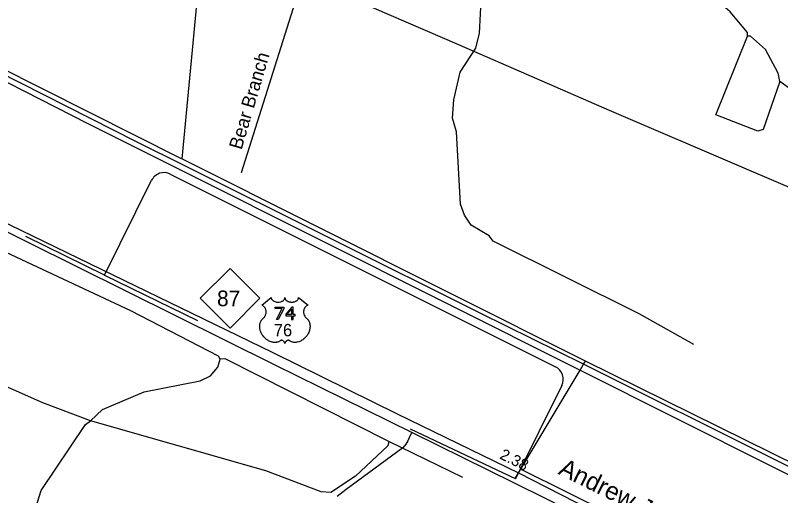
# Model space of a CAD drawing. Extents: x 2225501 to 2309677, y 165449 to 227696.
# Drawn here: x 2244504 to 2253045, y 199877 to 205240 of the extents above; entities that cross this region are included whole.
import ezdxf

# ---------------------------------------------------------------- set-up
doc = ezdxf.new("R2010")
doc.units = 0
for name, color, linetype in [('Black Area Fill Shapes', 7, 'Continuous'), ('Collision Diagram Indicator Injury CELL', 7, 'Continuous'), ('Old_Level_3', 7, 'Continuous'), ('Old_Level_46', 7, 'Continuous'), ('P_HYD_Ditch_Flow_Line', 7, 'Continuous'), ('P_HYD_Junction_Box_with_Slab_Lid_840_31_15_Dia-Top_CELL', 7, 'Continuous'), ('P_HYD_RipRap_Pad_876_02_18in_Outlet_With_Ditch-Top_CELL', 7, 'Continuous'), ('P_HYD_RipRap_Pad_876_02_18in_Outlet_With_Ditch_CELL', 7, 'Continuous'), ('Prop Support', 7, 'Continuous'), ('Raster_Level_0', 7, 'Continuous'), ('Scratch_Level_1', 7, 'Continuous'), ('Scratch_Level_2', 7, 'Continuous'), ('Typical Terminator CELL', 7, 'Continuous')]:
    doc.layers.add(name, color=color, linetype=linetype)

msp = doc.modelspace()

# ---------------------------------------------------------------- linework, layer by layer
at = {"layer": 'Black Area Fill Shapes'}
for points in [[(2244873.1, 206903.9), (2245139.4, 206787.1), (2246595.9, 206147.3), (2247912.2, 205580.4), (2249458.9, 204911.2), (2251132.3, 204181.1), (2252660.9, 203525.9), (2253800.5, 203037.4), (2255064.4, 202491.9), (2255394, 202351.2)], [(2246387.7, 203561.8), (2245857.2, 203826.2), (2244048.6, 204743.1), (2243731.3, 204902.7)], [(2243706.2, 204852.1), (2245311.8, 204031.6), (2246428.1, 203472.8)], [(2250845.6, 201345.2), (2249697.4, 201912.2), (2246387.7, 203561.8)], [(2246428.1, 203472.8), (2249284.4, 202042.9), (2250805.9, 201279)], [(2254290.5, 199620.9), (2252914.9, 200311.1), (2250919.7, 201308.6), (2250845.6, 201345.2)], [(2250805.9, 201279), (2252943.9, 200205.6), (2254260.8, 199546.4)]]:
    msp.add_lwpolyline(points, dxfattribs=at)
at = {"layer": 'Collision Diagram Indicator Injury CELL'}
for p, q in [((2246233.2, 203467.5), (2250532.4, 201316)), ((2245499.3, 202339.4), (2246025, 203397.8)), ((2245499.3, 202339.4), (2244623.1, 202770.9)), ((2245499.3, 202339.4), (2246537.6, 201834.2)), ((2250601.9, 201108.4), (2250084.5, 200066.8)), ((2250084.5, 200066.8), (2248914.6, 200621)), ((2250152, 200168.1), (2251904.7, 199305.8))]:
    msp.add_line(p, q, dxfattribs=at)
for centre, start, end in [((2246163.9, 203328.8), 63.41515, 153.58531), ((2250463.1, 201177.4), 333.58531, 63.41515)]:
    msp.add_arc(centre, 155, start, end, dxfattribs=at)
at = {"layer": 'Old_Level_3'}
for p, q in [((2246537.5, 205467.2), (2246362.6, 203636.4)), ((2246351.4, 203642.1), (2243753, 204946.6)), ((2246362.6, 203636.4), (2246351.4, 203642.1)), ((2250865.3, 201378), (2246362.6, 203636.4)), ((2250805.9, 201279), (2250845.6, 201345.2)), ((2250845.6, 201345.2), (2250865.3, 201378)), ((2253336.1, 200158.7), (2250865.3, 201378)), ((2250114.3, 200125.3), (2250805.9, 201279)), ((2248900.8, 200521.7), (2248883.2, 200488.2))]:
    msp.add_line(p, q, dxfattribs=at)
for points in [[(2248900.8, 200521.7), (2248926.6, 200570.6), (2248933.2, 200581.2)], [(2248883.2, 200488.2), (2248861.5, 200452.1), (2248829.9, 200411.9), (2248197.8, 199946.9), (2248095.2, 199869.5)], [(2250080.7, 200066.4), (2250086.1, 200078.3), (2250114.3, 200125.3)]]:
    msp.add_lwpolyline(points, dxfattribs=at)
at = {"layer": 'Old_Level_46'}
for points in [[(2256956.7, 196790), (2256924.7, 196796.5), (2256832.3, 196817.3), (2256652.3, 196875.8), (2256591.1, 196902.4), (2256480.1, 196951.1), (2256338.5, 197006.2), (2256282.6, 197031), (2254541.8, 197924.5), (2254210.5, 198073.2), (2253786.6, 198278.1), (2252185.6, 199073.8), (2250121.7, 200127.7), (2248768.8, 200789.1), (2247375.2, 201475.6), (2243675.2, 203270.8), (2243284.4, 203458.4), (2243017.1, 203588.4)], [(2242986.4, 203530.7), (2247394.3, 201340.7), (2248933.2, 200581.2), (2250061.9, 200025.4), (2252258.3, 198936.4), (2253668.1, 198237.8), (2254159.3, 197994.4), (2254220.9, 197964), (2255278.5, 197442.7), (2256250.7, 196963.5), (2256279.6, 196949.9), (2256416.4, 196885.1), (2256553.4, 196820.3), (2256635.4, 196787.9), (2256780.8, 196739.2), (2256905.8, 196709.8), (2256941.4, 196700.5), (2256960.1, 196697.4)]]:
    msp.add_lwpolyline(points, dxfattribs=at)
at = {"layer": 'P_HYD_Ditch_Flow_Line'}
for points in [[(2247499.4, 201961.7), (2247437.2, 201844.7), (2247417.4, 201844.7), (2247483.4, 201966), (2247405.3, 201966), (2247405.3, 201982.2), (2247499.4, 201982.2)], [(2247625.4, 201883.4), (2247625.4, 201898.2), (2247605, 201898.2), (2247605, 201982.2), (2247588, 201982.2), (2247521.4, 201904.7), (2247521.4, 201883.4), (2247587.2, 201883.4), (2247587.2, 201844.7), (2247605, 201844.7), (2247605, 201883.4)], [(2247587.2, 201898.2), (2247533.9, 201898.2), (2247587.2, 201960.3)]]:
    msp.add_lwpolyline(points, close=True, dxfattribs=at)
at = {"layer": 'P_HYD_Junction_Box_with_Slab_Lid_840_31_15_Dia-Top_CELL'}
for p, q in [((2246567.8, 202082.2), (2246900.8, 202415.2)), ((2246900.8, 202415.2), (2247233.8, 202082.2)), ((2246900.8, 201749.2), (2246567.8, 202082.2)), ((2247233.8, 202082.2), (2246900.8, 201749.2))]:
    msp.add_line(p, q, dxfattribs=at)
at = {"layer": 'P_HYD_RipRap_Pad_876_02_18in_Outlet_With_Ditch-Top_CELL'}
for p, q in [((2247253.8, 202004.1), (2247360.1, 202088.8)), ((2247360.1, 202088.8), (2247360.4, 202084.4)), ((2247360.4, 202084.4), (2247361.4, 202079.2)), ((2247511.1, 202080.3), (2247511.7, 202083.1)), ((2247511.7, 202083.1), (2247512.2, 202089)), ((2247512.2, 202089), (2247512.6, 202084.1)), ((2247512.6, 202084.1), (2247513.1, 202081)), ((2247662.6, 202078), (2247663.7, 202082.2)), ((2247663.7, 202082.2), (2247664.2, 202085.9)), ((2247664.2, 202085.9), (2247664.3, 202089.1)), ((2247664.3, 202089.1), (2247770.5, 202004.4)), ((2247257.1, 202002.8), (2247253.8, 202004.1)), ((2247262.3, 202000.2), (2247257.1, 202002.8)), ((2247267.7, 201996.9), (2247262.3, 202000.2)), ((2247272, 201993.9), (2247267.7, 201996.9)), ((2247361.4, 202079.2), (2247362.3, 202076.5)), ((2247362.3, 202076.5), (2247364.7, 202071.3)), ((2247364.7, 202071.3), (2247368.7, 202065.2)), ((2247368.7, 202065.2), (2247374.3, 202059.2)), ((2247374.3, 202059.2), (2247380.7, 202054)), ((2247380.7, 202054), (2247384.9, 202051.3)), ((2247384.9, 202051.3), (2247392.2, 202047.4)), ((2247392.2, 202047.4), (2247400.4, 202043.9)), ((2247400.4, 202043.9), (2247409.6, 202041.3)), ((2247409.6, 202041.3), (2247418.9, 202039.4)), ((2247418.9, 202039.4), (2247429.2, 202038.3)), ((2247429.2, 202038.3), (2247439.3, 202038.1)), ((2247439.3, 202038.1), (2247450.2, 202038.9)), ((2247450.2, 202038.9), (2247462.2, 202041.2)), ((2247462.2, 202041.2), (2247467.8, 202042.7)), ((2247467.8, 202042.7), (2247474, 202044.8)), ((2247474, 202044.8), (2247479.8, 202047.2)), ((2247479.8, 202047.2), (2247486.2, 202050.6)), ((2247486.2, 202050.6), (2247491.2, 202053.8)), ((2247491.2, 202053.8), (2247495.2, 202056.7)), ((2247495.2, 202056.7), (2247500.9, 202062.1)), ((2247500.9, 202062.1), (2247505.4, 202067.7)), ((2247505.4, 202067.7), (2247507.3, 202070.9)), ((2247507.3, 202070.9), (2247508.9, 202073.9)), ((2247508.9, 202073.9), (2247511.1, 202080.3)), ((2247513.1, 202081), (2247513.9, 202078)), ((2247513.9, 202078), (2247515.1, 202074.8)), ((2247515.1, 202074.8), (2247517.4, 202070.2)), ((2247517.4, 202070.2), (2247519.9, 202066.5)), ((2247519.9, 202066.5), (2247524.6, 202060.9)), ((2247524.6, 202060.9), (2247527.6, 202058.1)), ((2247527.6, 202058.1), (2247530.3, 202055.9)), ((2247530.3, 202055.9), (2247537.5, 202051)), ((2247537.5, 202051), (2247545.9, 202046.7)), ((2247545.9, 202046.7), (2247550.1, 202044.9)), ((2247550.1, 202044.9), (2247554.4, 202043.4)), ((2247554.4, 202043.4), (2247559.8, 202041.7)), ((2247559.8, 202041.7), (2247565.3, 202040.4)), ((2247565.3, 202040.4), (2247570.9, 202039.5)), ((2247570.9, 202039.5), (2247576.5, 202038.6)), ((2247576.5, 202038.6), (2247582.3, 202038.2)), ((2247582.3, 202038.2), (2247587, 202038.1)), ((2247587, 202038.1), (2247592.8, 202038.1)), ((2247592.8, 202038.1), (2247598.1, 202038.5)), ((2247598.1, 202038.5), (2247603.6, 202039.1)), ((2247603.6, 202039.1), (2247609.6, 202040.1)), ((2247609.6, 202040.1), (2247614.4, 202041.2)), ((2247614.4, 202041.2), (2247620.8, 202042.9)), ((2247620.8, 202042.9), (2247626.6, 202044.9)), ((2247626.6, 202044.9), (2247631.7, 202047.1)), ((2247631.7, 202047.1), (2247638.3, 202050.6)), ((2247638.3, 202050.6), (2247643.6, 202053.9)), ((2247643.6, 202053.9), (2247647.5, 202057.1)), ((2247647.5, 202057.1), (2247652.2, 202061.3)), ((2247652.2, 202061.3), (2247656.5, 202066.4)), ((2247656.5, 202066.4), (2247659.1, 202070.1)), ((2247659.1, 202070.1), (2247660.9, 202073.9)), ((2247660.9, 202073.9), (2247662.6, 202078)), ((2247757.7, 201998), (2247750.4, 201992.8)), ((2247762.3, 202000.7), (2247757.7, 201998)), ((2247768, 202003.5), (2247762.3, 202000.7)), ((2247770.5, 202004.4), (2247768, 202003.5)), ((2247276.5, 201990.4), (2247272, 201993.9)), ((2247281.2, 201985.6), (2247276.5, 201990.4)), ((2247285.9, 201980.4), (2247281.2, 201985.6)), ((2247290.4, 201973.9), (2247285.9, 201980.4)), ((2247294.5, 201966.9), (2247290.4, 201973.9)), ((2247296.9, 201961.8), (2247294.5, 201966.9)), ((2247299.6, 201954.7), (2247296.9, 201961.8)), ((2247301.2, 201948.6), (2247299.6, 201954.7)), ((2247302.6, 201941.6), (2247301.2, 201948.6)), ((2247301.2, 201907.8), (2247302.5, 201914.2)), ((2247302.5, 201914.2), (2247303.3, 201920.3)), ((2247303.4, 201934.2), (2247302.6, 201941.6)), ((2247303.3, 201920.3), (2247303.6, 201927.9)), ((2247303.6, 201927.9), (2247303.4, 201934.2)), ((2247721.1, 201935.6), (2247720.8, 201931.1)), ((2247720.8, 201931.1), (2247720.8, 201926.6)), ((2247720.8, 201926.6), (2247721, 201921.9)), ((2247721, 201921.9), (2247721.4, 201917.4)), ((2247722.3, 201945.1), (2247721.1, 201935.6)), ((2247721.4, 201917.4), (2247722.3, 201912.7)), ((2247723.3, 201949.7), (2247722.3, 201945.1)), ((2247722.3, 201912.7), (2247723, 201908.5)), ((2247724.9, 201955.1), (2247723.3, 201949.7)), ((2247728.2, 201963.6), (2247724.9, 201955.1)), ((2247730.1, 201967.7), (2247728.2, 201963.6)), ((2247732.8, 201972.4), (2247730.1, 201967.7)), ((2247735.6, 201976.7), (2247732.8, 201972.4)), ((2247738.7, 201980.9), (2247735.6, 201976.7)), ((2247741.2, 201983.9), (2247738.7, 201980.9)), ((2247744.1, 201987), (2247741.2, 201983.9)), ((2247747.2, 201990), (2247744.1, 201987)), ((2247750.4, 201992.8), (2247747.2, 201990)), ((2247242.2, 201821), (2247245.7, 201828.1)), ((2247245.7, 201828.1), (2247249, 201833.9)), ((2247249, 201833.9), (2247253.2, 201840.2)), ((2247253.2, 201840.2), (2247257.4, 201845.5)), ((2247257.4, 201845.5), (2247262.8, 201851.4)), ((2247262.8, 201851.4), (2247268.5, 201856.8)), ((2247268.5, 201856.8), (2247273.6, 201861.1)), ((2247273.6, 201861.1), (2247279.8, 201867.1)), ((2247279.8, 201867.1), (2247283, 201870.7)), ((2247283, 201870.7), (2247286.9, 201875.8)), ((2247286.9, 201875.8), (2247289.9, 201880.5)), ((2247289.9, 201880.5), (2247292.4, 201884.7)), ((2247292.4, 201884.7), (2247295.6, 201890.9)), ((2247295.6, 201890.9), (2247297.6, 201895.6)), ((2247297.6, 201895.6), (2247300, 201902.7)), ((2247300, 201902.7), (2247301.2, 201907.8)), ((2247723, 201908.5), (2247724.3, 201903.4)), ((2247724.3, 201903.4), (2247726.2, 201897.5)), ((2247726.2, 201897.5), (2247728.5, 201891.8)), ((2247728.5, 201891.8), (2247733.4, 201882.6)), ((2247733.4, 201882.6), (2247739.6, 201873.2)), ((2247739.6, 201873.2), (2247744.1, 201867.9)), ((2247744.1, 201867.9), (2247748.5, 201863.4)), ((2247748.5, 201863.4), (2247755.1, 201857.9)), ((2247755.1, 201857.9), (2247758.6, 201854.7)), ((2247758.6, 201854.7), (2247762.7, 201850.6)), ((2247762.7, 201850.6), (2247769.3, 201842.9)), ((2247769.3, 201842.9), (2247772, 201839.3)), ((2247772, 201839.3), (2247774.8, 201835.2)), ((2247774.8, 201835.2), (2247777.3, 201831)), ((2247777.3, 201831), (2247779.8, 201826.5)), ((2247779.8, 201826.5), (2247781.8, 201822.5)), ((2247231.2, 201769.6), (2247231.5, 201776.8)), ((2247231.4, 201761), (2247231.2, 201769.6)), ((2247232, 201751.7), (2247231.4, 201761)), ((2247231.5, 201776.8), (2247232.3, 201785.1)), ((2247233.2, 201742.8), (2247232, 201751.7)), ((2247232.3, 201785.1), (2247233.7, 201794)), ((2247234.4, 201736.3), (2247233.2, 201742.8)), ((2247233.7, 201794), (2247235.4, 201801.6)), ((2247235.4, 201801.6), (2247236.9, 201807)), ((2247236.9, 201807), (2247239.2, 201813.7)), ((2247239.2, 201813.7), (2247242.2, 201821)), ((2247781.8, 201822.5), (2247785.5, 201813.4)), ((2247785.5, 201813.4), (2247788.3, 201804.5)), ((2247788.3, 201804.5), (2247789.5, 201799.9)), ((2247789.5, 201799.9), (2247791.5, 201789.5)), ((2247792.1, 201750.1), (2247789.9, 201736.5)), ((2247791.5, 201789.5), (2247792.2, 201784.3)), ((2247793.1, 201761.8), (2247792.1, 201750.1)), ((2247792.2, 201784.3), (2247793.1, 201774.1)), ((2247793.1, 201774.1), (2247793.1, 201761.8)), ((2247236.4, 201727.2), (2247234.4, 201736.3)), ((2247237.9, 201722), (2247236.4, 201727.2)), ((2247240.5, 201713.9), (2247237.9, 201722)), ((2247243.7, 201705.2), (2247240.5, 201713.9)), ((2247247.7, 201695.8), (2247243.7, 201705.2)), ((2247250.8, 201689.4), (2247247.7, 201695.8)), ((2247256.4, 201679.1), (2247250.8, 201689.4)), ((2247260.3, 201672.7), (2247256.4, 201679.1)), ((2247266.3, 201663.9), (2247260.3, 201672.7)), ((2247275.6, 201651.9), (2247266.3, 201663.9)), ((2247754, 201658.9), (2247747.5, 201650.7)), ((2247759.6, 201666.6), (2247754, 201658.9)), ((2247764.1, 201673.2), (2247759.6, 201666.6)), ((2247767.9, 201679.4), (2247764.1, 201673.2)), ((2247773.5, 201689.7), (2247767.9, 201679.4)), ((2247777.8, 201698.5), (2247773.5, 201689.7)), ((2247782.6, 201710.6), (2247777.8, 201698.5)), ((2247785.3, 201718.9), (2247782.6, 201710.6)), ((2247788.1, 201728.4), (2247785.3, 201718.9)), ((2247789.9, 201736.5), (2247788.1, 201728.4)), ((2247281.5, 201645.1), (2247275.6, 201651.9)), ((2247291.6, 201634.9), (2247281.5, 201645.1)), ((2247298.5, 201628.6), (2247291.6, 201634.9)), ((2247307.9, 201621), (2247298.5, 201628.6)), ((2247320.3, 201612.4), (2247307.9, 201621)), ((2247330.9, 201606.3), (2247320.3, 201612.4)), ((2247337.6, 201602.9), (2247330.9, 201606.3)), ((2247347.3, 201598.7), (2247337.6, 201602.9)), ((2247355, 201595.7), (2247347.3, 201598.7)), ((2247362.2, 201593.5), (2247355, 201595.7)), ((2247369.3, 201591.6), (2247362.2, 201593.5)), ((2247375.9, 201590.1), (2247369.3, 201591.6)), ((2247383.9, 201588.9), (2247375.9, 201590.1)), ((2247390.4, 201588.3), (2247383.9, 201588.9)), ((2247396, 201587.9), (2247390.4, 201588.3)), ((2247402, 201587.8), (2247396, 201587.9)), ((2247407.7, 201588), (2247402, 201587.8)), ((2247414, 201588.6), (2247407.7, 201588)), ((2247419.9, 201589.5), (2247414, 201588.6)), ((2247426.6, 201590.8), (2247419.9, 201589.5)), ((2247433.2, 201592.5), (2247426.6, 201590.8)), ((2247439.2, 201594.5), (2247433.2, 201592.5)), ((2247444.3, 201596.5), (2247439.2, 201594.5)), ((2247448.7, 201598.6), (2247444.3, 201596.5)), ((2247454.6, 201601.7), (2247448.7, 201598.6)), ((2247459.5, 201604.8), (2247454.6, 201601.7)), ((2247464.1, 201607.9), (2247459.5, 201604.8)), ((2247468.9, 201611.4), (2247464.1, 201607.9)), ((2247472.4, 201612.2), (2247468.9, 201611.4)), ((2247475, 201612.2), (2247472.4, 201612.2)), ((2247478.1, 201612), (2247475, 201612.2)), ((2247482, 201611), (2247478.1, 201612)), ((2247485.1, 201609.9), (2247482, 201611)), ((2247488.5, 201608.1), (2247485.1, 201609.9)), ((2247492.8, 201605.5), (2247488.5, 201608.1)), ((2247496.8, 201602.3), (2247492.8, 201605.5)), ((2247500.1, 201599.1), (2247496.8, 201602.3)), ((2247503.8, 201594.8), (2247500.1, 201599.1)), ((2247506.2, 201591.5), (2247503.8, 201594.8)), ((2247508.4, 201587.7), (2247506.2, 201591.5)), ((2247510.4, 201583.3), (2247508.4, 201587.7)), ((2247512.1, 201576.6), (2247510.4, 201583.3)), ((2247513.3, 201581.9), (2247512.1, 201576.6)), ((2247514.7, 201585.5), (2247513.3, 201581.9)), ((2247516, 201588.3), (2247514.7, 201585.5)), ((2247519.7, 201594.1), (2247516, 201588.3)), ((2247521.6, 201596.4), (2247519.7, 201594.1)), ((2247524.1, 201599.2), (2247521.6, 201596.4)), ((2247527.7, 201602.7), (2247524.1, 201599.2)), ((2247530.8, 201605.1), (2247527.7, 201602.7)), ((2247534.7, 201607.7), (2247530.8, 201605.1)), ((2247537.6, 201609.2), (2247534.7, 201607.7)), ((2247542.5, 201611.2), (2247537.6, 201609.2)), ((2247547.3, 201612.2), (2247542.5, 201611.2)), ((2247552.4, 201611.9), (2247547.3, 201612.2)), ((2247554.5, 201611.4), (2247552.4, 201611.9)), ((2247558.3, 201609.4), (2247554.5, 201611.4)), ((2247571.5, 201601.1), (2247558.3, 201609.4)), ((2247579.2, 201597.2), (2247571.5, 201601.1)), ((2247586.9, 201594.2), (2247579.2, 201597.2)), ((2247595.4, 201591.7), (2247586.9, 201594.2)), ((2247603.5, 201590), (2247595.4, 201591.7)), ((2247611.3, 201588.9), (2247603.5, 201590)), ((2247619.5, 201588.3), (2247611.3, 201588.9)), ((2247627.8, 201588.3), (2247619.5, 201588.3)), ((2247633.9, 201588.6), (2247627.8, 201588.3)), ((2247640.3, 201589.3), (2247633.9, 201588.6)), ((2247647.1, 201590.3), (2247640.3, 201589.3)), ((2247652.8, 201591.5), (2247647.1, 201590.3)), ((2247668.5, 201595.8), (2247652.8, 201591.5)), ((2247677.9, 201599.4), (2247668.5, 201595.8)), ((2247685.2, 201602.5), (2247677.9, 201599.4)), ((2247693.4, 201606.7), (2247685.2, 201602.5)), ((2247703.1, 201612.3), (2247693.4, 201606.7)), ((2247712.8, 201618.8), (2247703.1, 201612.3)), ((2247720, 201624.2), (2247712.8, 201618.8)), ((2247725, 201628.4), (2247720, 201624.2)), ((2247733.3, 201635.8), (2247725, 201628.4)), ((2247739.6, 201642.1), (2247733.3, 201635.8)), ((2247747.5, 201650.7), (2247739.6, 201642.1))]:
    msp.add_line(p, q, dxfattribs=at)
at = {"layer": 'Prop Support'}
for p, q in [((2253195.7, 204386.4), (2253036.6, 204501.1)), ((2249498.5, 200081.3), (2248670.7, 200482.7))]:
    msp.add_line(p, q, dxfattribs=at)
for points in [[(2252076.2, 201566), (2251466.5, 201907.6), (2249835.6, 202716.8), (2249793.5, 202776.6), (2249592.6, 202898.7), (2249516.7, 203008.3), (2249473.6, 203130.6), (2249425.7, 203938.4), (2249382.6, 204090.1), (2249397.6, 204296.5), (2249469.5, 204606.7), (2249642.6, 204872.3), (2249682.6, 205042.1), (2249704.5, 205474.6), (2249752.5, 205657.4), (2249967.6, 205866.4), (2250324.6, 206062.8), (2250506.7, 206239.7), (2250596.7, 206365.9), (2250657.6, 207040.4), (2250796.6, 207355.8), (2251027.5, 207633.4), (2251093.6, 207802.7)], [(2252673.7, 205006.7), (2252673.7, 205049.4), (2252479.7, 205279.5), (2252194.7, 205527.8), (2251992.7, 205826.9), (2251806.7, 206181.5), (2251481.7, 207171.9), (2251394.6, 207678.7)], [(2253036.6, 204501.1), (2252848.6, 203966.8), (2252790.6, 203948.3), (2252322.6, 204127.9), (2252673.7, 205006.7)], [(2253036.6, 204501.1), (2253018.6, 204593.3), (2252874.6, 204858.5), (2252706.7, 205006.1), (2252673.7, 205006.7)], [(2246788.5, 201401.8), (2246771.7, 201434.9), (2245792.5, 201942.7), (2243928.6, 202812.2), (2242873.9, 203319.5)], [(2245344.5, 200714.8), (2244810.6, 200912.2), (2242878.6, 201769.9), (2242325.5, 202164.5), (2242286.6, 202217.1)], [(2245344.5, 200714.8), (2245477.6, 200840.2), (2245941.6, 201037.8), (2246565.6, 201160.1), (2246681.7, 201216.9), (2246764.5, 201310.4), (2246788.5, 201401.8)], [(2248670.7, 200482.7), (2246847.5, 201403.9), (2246788.5, 201401.8)], [(2252070.6, 195171.6), (2251794.6, 195311.4), (2246064.7, 198280), (2246029.6, 198464.4), (2245929.5, 198522.2), (2245336.5, 198648.5), (2245069.5, 198781.7), (2244758.5, 199096.1), (2244665.6, 199294.7), (2244671.5, 199543.8), (2244793.5, 199935.1), (2245286.5, 200673.3), (2245344.5, 200714.8)], [(2248670.7, 200482.7), (2248662.7, 200433.7), (2248298.5, 200096.4), (2248025.6, 199911.5), (2247916.7, 199920.1), (2247298.7, 200155.2), (2245344.5, 200714.8)]]:
    msp.add_lwpolyline(points, dxfattribs=at)
at = {"layer": 'Typical Terminator CELL'}
msp.add_lwpolyline([(2247029.6, 203486.5), (2247695.6, 205599.1), (2247693.6, 205858.3), (2247634.5, 205941.4), (2247683.5, 206097.9), (2248177.5, 206754.1), (2248722.5, 207356.9), (2248779.5, 207500.1), (2248846.6, 207551.3), (2249271.7, 208494.2)], dxfattribs=at)

# ---------------------------------------------------------------- texts
at = {"layer": 'P_HYD_Ditch_Flow_Line'}
msp.add_text('76', height=137.5, dxfattribs=at).set_placement((2247388.8, 201656.8))
at = {"layer": 'P_HYD_RipRap_Pad_876_02_18in_Outlet_With_Ditch_CELL'}
msp.add_text('87', height=175, dxfattribs=at).set_placement((2246754.9, 201992.5))
at = {"layer": 'Raster_Level_0'}
msp.add_text('2.38', height=125, rotation=333.57391, dxfattribs=at).set_placement((2249900, 200295.9))
at = {"layer": 'Scratch_Level_1'}
msp.add_text('Bear Branch', height=150, rotation=73.59195, dxfattribs=at).set_placement((2247028.8, 203731.6))
at = {"layer": 'Scratch_Level_2'}
msp.add_text('Andrew Jackson Hwy.', height=200, rotation=333.73111, dxfattribs=at).set_placement((2250552.6, 200122.7))

doc.saveas('drawing.dxf')
